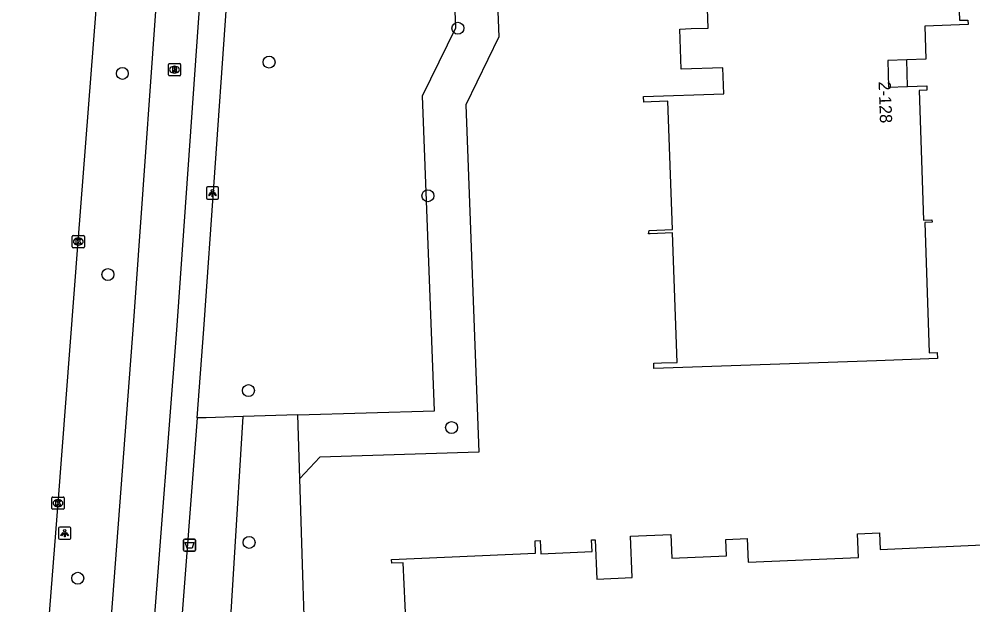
# Model space of a CAD drawing. Extents: x 161243 to 161752, y 384138 to 384885.
# Drawn here: x 161249.9 to 161327.9, y 384187.6 to 384235.5 of the extents above; entities that cross this region are included whole.
import ezdxf

# ---------------------------------------------------------------- set-up
doc = ezdxf.new("R2010")
doc.units = 0
for name, color, linetype in [('IMGEO_Afvalbak', 7, 'Continuous'), ('IMGEO_Boom', 7, 'Continuous'), ('IMGEO_Fietspad_gesloten', 7, 'Continuous'), ('IMGEO_Groenvoorziening', 7, 'Continuous'), ('IMGEO_Kolk', 7, 'Continuous'), ('IMGEO_Lichtpunt', 7, 'Continuous'), ('IMGEO_OVBaan_gesloten', 7, 'Continuous'), ('IMGEO_Pand', 7, 'Continuous'), ('IMGEO_Pand_nummerreeks', 7, 'Continuous'), ('IMGEO_Pand_overbouw', 7, 'Continuous'), ('IMGEO_Rioolput', 7, 'Continuous'), ('IMGEO_Voetpad_open', 7, 'Continuous')]:
    doc.layers.add(name, color=color, linetype=linetype)

msp = doc.modelspace()

# ---------------------------------------------------------------- linework, layer by layer
at = {"layer": 'IMGEO_Afvalbak'}
for p, q in [((161263.481, 384193.032), (161264.271, 384193.032)), ((161264.271, 384193.032), (161263.481, 384193.032)), ((161263.381, 384192.132), (161263.381, 384192.932)), ((161263.381, 384192.932), (161263.381, 384192.132)), ((161264.371, 384192.932), (161264.371, 384192.132)), ((161264.371, 384192.132), (161264.371, 384192.932)), ((161264.271, 384192.032), (161263.481, 384192.032)), ((161263.481, 384192.032), (161264.271, 384192.032))]:
    msp.add_line(p, q, dxfattribs=at)
msp.add_lwpolyline([(161263.524, 384192.746), (161264.228, 384192.746), (161264.079, 384192.276), (161263.673, 384192.276), (161263.524, 384192.746)], dxfattribs=at)
for centre, start, end in [((161263.481, 384192.932), 90, 180), ((161263.481, 384192.932), 90, 180), ((161264.271, 384192.932), 0, 90), ((161264.271, 384192.932), 360, 90), ((161263.481, 384192.132), 180, 270), ((161263.481, 384192.132), 180, 270), ((161264.271, 384192.132), 270, 0), ((161264.271, 384192.132), 270, 0)]:
    msp.add_arc(centre, 0.1, start, end, dxfattribs=at)
at = {"layer": 'IMGEO_Boom'}
for centre in [(161285.821, 384234.783), (161270.379, 384232.015), (161258.379, 384231.099), (161283.361, 384221.097), (161257.204, 384214.656), (161268.691, 384205.17), (161285.305, 384202.149), (161268.746, 384192.763), (161254.733, 384189.829)]:
    msp.add_circle(centre, 0.489, dxfattribs=at)
at = {"layer": 'IMGEO_Fietspad_gesloten'}
for points in [[(161258.742, 384157.135), (161260.876, 384184.71), (161262.854, 384210.484), (161266.448, 384261.586), (161267.146, 384270.325), (161268.291, 384284.663), (161268.569, 384287.683), (161268.583, 384287.814)], [(161263.994, 384275.849), (161263.983, 384275.709), (161263.143, 384264.813), (161262.927, 384262.016), (161262.305, 384253.304), (161261.604, 384243.474), (161259.279, 384210.879), (161257.318, 384184.907), (161257.099, 384182.165), (161256.945, 384180.975), (161255.727, 384175.693), (161255.111, 384172.583), (161254.402, 384168.209), (161253.797, 384163.617), (161252.937, 384155.312)]]:
    msp.add_lwpolyline(points, dxfattribs=at)
at = {"layer": 'IMGEO_Groenvoorziening'}
for points in [[(161300.059, 384300.607), (161300.109, 384299.408), (161291.319, 384298.89), (161286.795, 384293.851), (161288.542, 384250), (161289.176, 384234.089), (161286.463, 384228.528), (161287.535, 384200.127), (161274.519, 384199.728), (161272.888, 384197.971)], [(161272.718, 384203.175), (161283.905, 384203.517), (161282.932, 384229.273), (161285.644, 384234.831), (161284.385, 384266.432)], [(161272.718, 384203.175), (161268.25, 384203.038)], [(161272.888, 384197.971), (161272.718, 384203.175)], [(161268.25, 384203.038), (161265.239, 384202.946), (161264.495, 384202.929)], [(161266.792, 384179.062), (161268.25, 384203.038)], [(161273.844, 384168.781), (161273.175, 384189.215), (161272.888, 384197.971)]]:
    msp.add_lwpolyline(points, dxfattribs=at)
at = {"layer": 'IMGEO_Kolk'}
for p, q in [((161254.277, 384216.921), (161254.277, 384217.773)), ((161254.352, 384217.847), (161255.204, 384217.847)), ((161254.765, 384217.627), (161254.79, 384217.627)), ((161255.278, 384217.773), (161255.278, 384216.921)), ((161255.204, 384216.847), (161254.352, 384216.847)), ((161254.788, 384217.067), (161254.763, 384217.067)), ((161252.616, 384195.544), (161252.616, 384196.396)), ((161252.691, 384196.47), (161253.543, 384196.47)), ((161253.104, 384196.25), (161253.129, 384196.25)), ((161253.617, 384196.396), (161253.617, 384195.544)), ((161253.543, 384195.47), (161252.691, 384195.47)), ((161253.127, 384195.69), (161253.102, 384195.69))]:
    msp.add_line(p, q, dxfattribs=at)
for points in [[(161254.277, 384216.921), (161254.277, 384217.773)], [(161254.352, 384217.847), (161255.204, 384217.847)], [(161254.598, 384217.547), (161254.721, 384217.547), (161254.721, 384217.396), (161254.851, 384217.547), (161255.015, 384217.547), (161254.869, 384217.396), (161255.022, 384217.147), (161254.87, 384217.147), (161254.785, 384217.311), (161254.721, 384217.244), (161254.721, 384217.147), (161254.598, 384217.147), (161254.598, 384217.547)], [(161255.278, 384217.773), (161255.278, 384216.921)], [(161255.204, 384216.847), (161254.352, 384216.847)], [(161252.616, 384195.544), (161252.616, 384196.396)], [(161252.691, 384196.47), (161253.543, 384196.47)], [(161252.937, 384196.17), (161253.06, 384196.17), (161253.06, 384196.019), (161253.19, 384196.17), (161253.354, 384196.17), (161253.208, 384196.019), (161253.361, 384195.77), (161253.209, 384195.77), (161253.124, 384195.934), (161253.06, 384195.867), (161253.06, 384195.77), (161252.937, 384195.77), (161252.937, 384196.17)], [(161253.617, 384196.396), (161253.617, 384195.544)], [(161253.543, 384195.47), (161252.691, 384195.47)]]:
    msp.add_lwpolyline(points, dxfattribs=at)
for centre, start, end in [((161254.354, 384217.771), 91.55205, 178.44795), ((161254.354, 384217.771), 91.55205, 178.44795), ((161255.202, 384217.771), 1.55205, 88.44795), ((161255.202, 384217.771), 1.55205, 88.44795), ((161254.354, 384216.923), 181.55205, 268.44795), ((161254.354, 384216.923), 181.55205, 268.44795), ((161255.202, 384216.923), 271.55205, 358.44795), ((161255.202, 384216.923), 271.55205, 358.44795), ((161252.693, 384196.394), 91.55205, 178.44795), ((161252.693, 384196.394), 91.55205, 178.44795), ((161253.541, 384196.394), 1.55205, 88.44795), ((161253.541, 384196.394), 1.55205, 88.44795), ((161252.693, 384195.546), 181.55205, 268.44795), ((161252.693, 384195.546), 181.55205, 268.44795), ((161253.541, 384195.546), 271.55205, 358.44795), ((161253.541, 384195.546), 271.55205, 358.44795)]:
    msp.add_arc(centre, 0.0765, start, end, dxfattribs=at)
for centre, major_axis, ratio, start_param, end_param in [((161254.764, 384217.347), (-0.387, 0.002), 0.722429, 4.712389, 7.853982), ((161254.789, 384217.347), (-0.39, 0.002), 0.717154, 1.570796, 4.712389), ((161253.103, 384195.97), (-0.387, 0.002), 0.722429, 4.712389, 7.853982), ((161253.128, 384195.97), (-0.39, 0.002), 0.717154, 1.570796, 4.712389)]:
    msp.add_ellipse(centre, major_axis=major_axis, ratio=ratio, start_param=start_param, end_param=end_param, dxfattribs=at)
at = {"layer": 'IMGEO_Lichtpunt'}
for p, q in [((161265.252, 384221.721), (161265.252, 384220.914)), ((161265.252, 384221.721), (161265.252, 384220.914)), ((161266.154, 384221.816), (161265.346, 384221.816)), ((161266.154, 384221.816), (161265.346, 384221.816)), ((161266.248, 384220.914), (161266.248, 384221.721)), ((161266.248, 384220.914), (161266.248, 384221.721)), ((161265.346, 384220.82), (161266.154, 384220.82)), ((161265.346, 384220.82), (161266.154, 384220.82)), ((161253.17, 384193.918), (161253.17, 384193.111)), ((161253.17, 384193.918), (161253.17, 384193.111)), ((161254.072, 384194.013), (161253.264, 384194.013)), ((161254.072, 384194.013), (161253.264, 384194.013)), ((161254.166, 384193.111), (161254.166, 384193.918)), ((161254.166, 384193.111), (161254.166, 384193.918)), ((161253.264, 384193.017), (161254.072, 384193.017)), ((161253.264, 384193.017), (161254.072, 384193.017))]:
    msp.add_line(p, q, dxfattribs=at)
for points in [[(161265.626, 384221.385), (161265.665, 384221.357), (161265.477, 384221.095), (161265.439, 384221.122), (161265.626, 384221.385)], [(161265.728, 384221.337), (161265.775, 384221.337), (161265.775, 384221.015), (161265.728, 384221.015), (161265.728, 384221.337)], [(161265.838, 384221.357), (161265.876, 384221.384), (161266.063, 384221.122), (161266.024, 384221.094), (161265.838, 384221.357)], [(161253.544, 384193.582), (161253.583, 384193.554), (161253.395, 384193.292), (161253.357, 384193.319), (161253.544, 384193.582)], [(161253.646, 384193.534), (161253.693, 384193.534), (161253.693, 384193.212), (161253.646, 384193.212), (161253.646, 384193.534)], [(161253.756, 384193.554), (161253.794, 384193.581), (161253.981, 384193.319), (161253.942, 384193.291), (161253.756, 384193.554)]]:
    msp.add_lwpolyline(points, dxfattribs=at)
for centre in [(161265.751, 384221.519), (161253.669, 384193.716)]:
    msp.add_circle(centre, 0.0994, dxfattribs=at)
for centre, start, end in [((161265.346, 384221.721), 90, 180), ((161265.346, 384221.721), 90, 180), ((161266.154, 384221.721), 0, 90), ((161266.154, 384221.721), 0, 90), ((161265.346, 384220.914), 180, 270), ((161265.346, 384220.914), 180, 270), ((161266.154, 384220.914), 270, 0), ((161266.154, 384220.914), 270, 360), ((161253.264, 384193.918), 90, 180), ((161253.264, 384193.918), 90, 180), ((161254.072, 384193.918), 0, 90), ((161254.072, 384193.918), 0, 90), ((161253.264, 384193.111), 180, 270), ((161253.264, 384193.111), 180, 270), ((161254.072, 384193.111), 270, 0), ((161254.072, 384193.111), 270, 360)]:
    msp.add_arc(centre, 0.0946, start, end, dxfattribs=at)
at = {"layer": 'IMGEO_OVBaan_gesloten'}
msp.add_lwpolyline([(161249.934, 384156.079), (161249.949, 384156.206), (161250.106, 384158.053), (161251.316, 384173.143), (161251.591, 384176.567), (161253.117, 384195.97), (161254.778, 384217.347), (161256.24, 384236.299), (161258.002, 384258.664), (161259.312, 384275.054), (161259.367, 384276.07), (161259.381, 384276.22)], dxfattribs=at)
at = {"layer": 'IMGEO_Pand'}
for points in [[(161326.465, 384246.028), (161326.83, 384235.436), (161327.526, 384235.46), (161327.539, 384235.082), (161324.002, 384234.96), (161324.096, 384232.248), (161322.519, 384232.194), (161320.969, 384232.141), (161321.044, 384229.963), (161322.593, 384230.016), (161324.153, 384230.07), (161324.164, 384229.729), (161323.527, 384229.707), (161323.892, 384219.105), (161324.585, 384219.129), (161324.592, 384218.925), (161323.997, 384218.905), (161324.363, 384208.262), (161325.017, 384208.284), (161325.035, 384207.782), (161320.038, 384207.61), (161301.847, 384206.983), (161301.832, 384207.404), (161302.463, 384207.426), (161303.737, 384207.47), (161303.372, 384218.053), (161301.539, 384217.989), (161301.411, 384217.985), (161301.457, 384218.263), (161303.354, 384218.328), (161302.993, 384228.815), (161301.62, 384228.768), (161301.024, 384228.748), (161301.009, 384229.194), (161307.562, 384229.42), (161307.488, 384231.559), (161304.07, 384231.441), (161303.956, 384234.722), (161304.884, 384234.754), (161306.273, 384234.801), (161305.917, 384245.154)], [(161281.576, 384185.868), (161281.347, 384191.098), (161280.41, 384191.057), (161280.397, 384191.359), (161292.171, 384191.875), (161292.126, 384192.895), (161292.552, 384192.914), (161292.599, 384191.837), (161296.788, 384192.021), (161296.746, 384192.96), (161297.037, 384192.973), (161297.178, 384189.766), (161300.068, 384189.893), (161299.92, 384193.264), (161303.239, 384193.409), (161303.324, 384191.466), (161307.782, 384191.662), (161307.723, 384193.002), (161309.468, 384193.078), (161309.553, 384191.142), (161318.586, 384191.538), (161318.502, 384193.456), (161320.301, 384193.535), (161320.36, 384192.186), (161329.341, 384192.58)]]:
    msp.add_lwpolyline(points, dxfattribs=at)
at = {"layer": 'IMGEO_Pand_overbouw'}
msp.add_lwpolyline([(161322.519, 384232.194), (161320.969, 384232.141), (161321.044, 384229.963), (161322.593, 384230.016)], close=True, dxfattribs=at)
at = {"layer": 'IMGEO_Rioolput'}
for p, q in [((161262.145, 384230.974), (161262.145, 384231.826)), ((161262.22, 384231.9), (161263.072, 384231.9)), ((161262.633, 384231.68), (161262.658, 384231.68)), ((161263.146, 384231.826), (161263.146, 384230.974)), ((161263.072, 384230.9), (161262.22, 384230.9)), ((161262.656, 384231.12), (161262.631, 384231.12))]:
    msp.add_line(p, q, dxfattribs=at)
for points in [[(161262.145, 384230.974), (161262.145, 384231.826)], [(161262.22, 384231.9), (161263.072, 384231.9)], [(161262.734, 384231.598), (161262.482, 384231.6), (161262.482, 384231.2)], [(161262.482, 384231.2), (161262.606, 384231.2), (161262.606, 384231.362), (161262.617, 384231.362)], [(161262.66, 384231.519), (161262.606, 384231.519), (161262.606, 384231.438)], [(161262.606, 384231.438), (161262.658, 384231.438)], [(161262.664, 384231.333), (161262.735, 384231.2), (161262.875, 384231.2), (161262.81, 384231.326)], [(161263.146, 384231.826), (161263.146, 384230.974)], [(161263.072, 384230.9), (161262.22, 384230.9)]]:
    msp.add_lwpolyline(points, dxfattribs=at)
for centre, radius, start, end in [((161262.222, 384231.824), 0.0765, 91.55205, 178.44795), ((161262.222, 384231.824), 0.0765, 91.55205, 178.44795), ((161262.616, 384231.309), 0.0533, 26.02933, 88.69889), ((161262.642, 384231.627), 0.19, 274.7715, 282.96867), ((161262.666, 384231.423), 0.0964, 77.00612, 93.18647), ((161262.68, 384231.48), 0.0378, 276.66336, 79.67722), ((161262.733, 384231.488), 0.109, 350.36119, 89.41601), ((161262.731, 384231.488), 0.112, 277.58423, 350.98172), ((161262.715, 384231.273), 0.108, 29.51342, 73.79051), ((161263.07, 384231.824), 0.0765, 1.55205, 88.44795), ((161263.07, 384231.824), 0.0765, 1.55205, 88.44795), ((161262.222, 384230.976), 0.0765, 181.55205, 268.44795), ((161262.222, 384230.976), 0.0765, 181.55205, 268.44795), ((161263.07, 384230.976), 0.0765, 271.55205, 358.44795), ((161263.07, 384230.976), 0.0765, 271.55205, 358.44795)]:
    msp.add_arc(centre, radius, start, end, dxfattribs=at)
for centre, major_axis, ratio, start_param, end_param in [((161262.632, 384231.4), (-0.387, 0.002), 0.722429, 4.712389, 7.853982), ((161262.657, 384231.4), (-0.39, 0.002), 0.717154, 1.570796, 4.712389)]:
    msp.add_ellipse(centre, major_axis=major_axis, ratio=ratio, start_param=start_param, end_param=end_param, dxfattribs=at)
at = {"layer": 'IMGEO_Voetpad_open'}
for points in [[(161264.495, 384202.929), (161265.049, 384210.182), (161268.653, 384261.442), (161269.116, 384267.426), (161270.314, 384267.335), (161270.33, 384267.547)], [(161264.495, 384202.929), (161263.087, 384184.499), (161261.07, 384158.294)]]:
    msp.add_lwpolyline(points, dxfattribs=at)

# ---------------------------------------------------------------- texts
at = {"layer": 'IMGEO_Pand_nummerreeks'}
msp.add_text('2-128', height=1, rotation=272.01087, dxfattribs=at).set_placement((161320.219, 384230.425))

doc.saveas('drawing.dxf')
